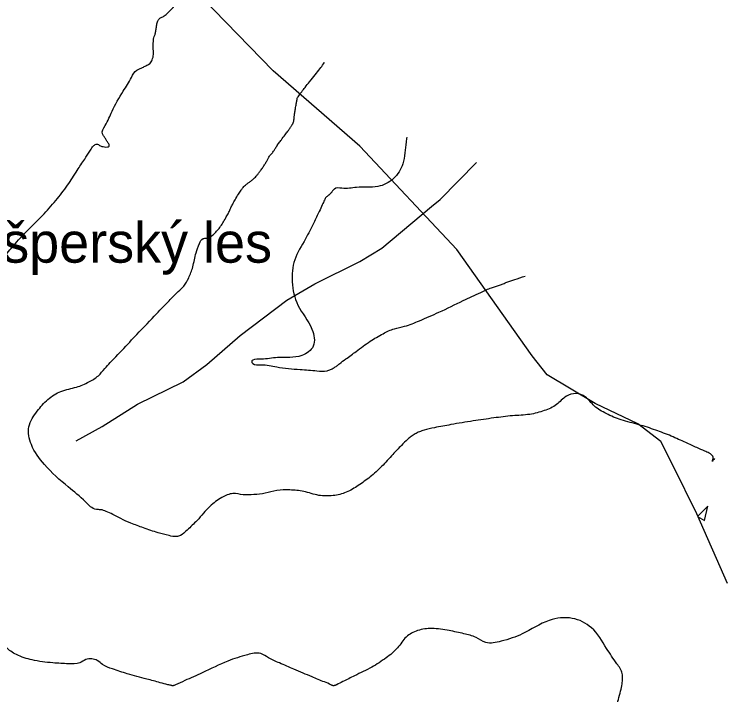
# Model space of a CAD drawing. Extents: x -478495 to -472450, y -1118050 to -1113745.
# Drawn here: x -473518.6 to -473165.3, y -1115365.2 to -1115027.8 of the extents above; entities that cross this region are included whole.
import ezdxf

# ---------------------------------------------------------------- set-up
doc = ezdxf.new("R2010")
doc.units = 0
for name, color, linetype in [('cesty', 7, 'Continuous'), ('hranice kú', 7, 'Continuous'), ('místní názvy', 7, 'Continuous'), ('ObPÚ', 7, 'Continuous'), ('vodní plochy', 7, 'Continuous'), ('Vrstevnice_vedlejsi', 7, 'Continuous')]:
    doc.layers.add(name, color=color, linetype=linetype)

msp = doc.modelspace()

# ---------------------------------------------------------------- linework, layer by layer
at = {"layer": 'cesty'}
msp.add_line((-473179.81, -1115276.83), (-473176.29, -1115278.72), dxfattribs=at)
msp.add_lwpolyline([(-473176.29, -1115278.72), (-473174.77, -1115271.65), (-473179.81, -1115276.83)], dxfattribs=at)
at = {"layer": 'hranice kú'}
for p, q in [((-473390.27, -1115055.8), (-473447.09, -1114996.95)), ((-473347.21, -1115093.26), (-473390.27, -1115055.8)), ((-473299.14, -1115144.38), (-473347.21, -1115093.26)), ((-473261.82, -1115197.18), (-473299.14, -1115144.38)), ((-473254.42, -1115206.59), (-473261.82, -1115197.18)), ((-473230.56, -1115220.72), (-473254.42, -1115206.59)), ((-473209.38, -1115230.81), (-473230.56, -1115220.72)), ((-473197.95, -1115239.55), (-473209.38, -1115230.81)), ((-473191.9, -1115251.66), (-473197.95, -1115239.55)), ((-473180.13, -1115275.53), (-473191.9, -1115251.66)), ((-473165, -1115309.94), (-473180.13, -1115275.53))]:
    msp.add_line(p, q, dxfattribs=at)
at = {"layer": 'ObPÚ'}
for p, q in [((-473390.27, -1115055.8), (-473447.09, -1114996.95)), ((-473347.21, -1115093.26), (-473390.27, -1115055.8)), ((-473299.14, -1115144.38), (-473347.21, -1115093.26)), ((-473261.82, -1115197.18), (-473299.14, -1115144.38)), ((-473254.42, -1115206.59), (-473261.82, -1115197.18)), ((-473230.56, -1115220.72), (-473254.42, -1115206.59)), ((-473209.38, -1115230.81), (-473230.56, -1115220.72)), ((-473197.95, -1115239.55), (-473209.38, -1115230.81)), ((-473191.9, -1115251.66), (-473197.95, -1115239.55)), ((-473180.13, -1115275.53), (-473191.9, -1115251.66)), ((-473165, -1115309.94), (-473180.13, -1115275.53))]:
    msp.add_line(p, q, dxfattribs=at)
at = {"layer": 'vodní plochy'}
msp.add_lwpolyline([(-473487.84, -1115239.22), (-473474.91, -1115232.13), (-473457.38, -1115221.14), (-473434.84, -1115210.01), (-473423.02, -1115201.38), (-473406.6, -1115187.05), (-473383.37, -1115169.52), (-473369.46, -1115161.45), (-473347.2, -1115150.46), (-473336.34, -1115143.79), (-473311.68, -1115123.16), (-473307.4, -1115119.58), (-473289.33, -1115101.23)], dxfattribs=at)
at = {"layer": 'Vrstevnice_vedlejsi'}
for points in [[(-473446.07, -1115029.56), (-473444.61, -1115028.92), (-473442.9, -1115027.63), (-473440.94, -1115025.69), (-473438.73, -1115023.11), (-473437.44, -1115020.95), (-473437.07, -1115019.2), (-473437.61, -1115017.87), (-473438.22, -1115015.34), (-473438.91, -1115011.62), (-473439.67, -1115006.71), (-473440.23, -1115003.19), (-473440.58, -1115001.06), (-473440.73, -1115000.32), (-473440.83, -1114999.79), (-473440.89, -1114999.47), (-473440.89, -1114999.35), (-473440.89, -1114999.26), (-473440.88, -1114999.19), (-473440.87, -1114999.14), (-473441.82, -1114996.21), (-473443.73, -1114990.4), (-473446.61, -1114981.71), (-473449.79, -1114974.48), (-473453.27, -1114968.69), (-473457.05, -1114964.34), (-473458.85, -1114958.61), (-473458.98, -1114956.64)], [(-473650.09, -1115300.41), (-473650.27, -1115300.33), (-473651.2, -1115299.89), (-473652.87, -1115299.07), (-473655.28, -1115297.89), (-473656.7, -1115296.84), (-473657.11, -1115295.91), (-473656.52, -1115295.12), (-473655.22, -1115293.42), (-473653.2, -1115290.82), (-473650.48, -1115287.31), (-473648.64, -1115284.71), (-473647.7, -1115283.01), (-473647.65, -1115282.22), (-473647.4, -1115281.54), (-473646.94, -1115280.96), (-473646.29, -1115280.49), (-473645.68, -1115279.77), (-473645.12, -1115278.79), (-473644.61, -1115277.57), (-473643.82, -1115276.53), (-473642.73, -1115275.69), (-473641.37, -1115275.03), (-473636.09, -1115270.78), (-473626.9, -1115262.92), (-473613.8, -1115251.46), (-473605.02, -1115243.63), (-473600.54, -1115239.44), (-473600.38, -1115238.88), (-473600.08, -1115237.64), (-473599.62, -1115235.74), (-473599.03, -1115233.18), (-473598.49, -1115231.28), (-473597.99, -1115230.06), (-473597.54, -1115229.51), (-473597.17, -1115229.12), (-473596.88, -1115228.88), (-473596.67, -1115228.79), (-473595.3, -1115227.08), (-473592.76, -1115223.73), (-473589.05, -1115218.76), (-473585.86, -1115213.91), (-473583.19, -1115209.19), (-473581.03, -1115204.6), (-473578.54, -1115200.48), (-473575.73, -1115196.85), (-473572.58, -1115193.71), (-473569.44, -1115191.31), (-473566.29, -1115189.66), (-473563.15, -1115188.77), (-473557.95, -1115185.07), (-473550.71, -1115178.58), (-473541.42, -1115169.29), (-473533.88, -1115161.21), (-473528.09, -1115154.34), (-473524.04, -1115148.68), (-473518.79, -1115142.34), (-473512.33, -1115135.34), (-473504.66, -1115127.67), (-473497.93, -1115120.09), (-473492.16, -1115112.61), (-473487.34, -1115105.23), (-473483.65, -1115099.59), (-473481.12, -1115095.71), (-473479.73, -1115093.58), (-473478.47, -1115092.39), (-473477.35, -1115092.14), (-473476.35, -1115092.82), (-473475.18, -1115093.3), (-473473.83, -1115093.56), (-473472.29, -1115093.61), (-473471.54, -1115093.21), (-473471.57, -1115092.35), (-473472.39, -1115091.04), (-473473.2, -1115089.74), (-473474.01, -1115088.45), (-473474.81, -1115087.18), (-473473.5, -1115083), (-473470.08, -1115075.94), (-473464.54, -1115065.97), (-473460.42, -1115059.14), (-473457.72, -1115055.46), (-473456.44, -1115054.91), (-473454.96, -1115054.2), (-473453.28, -1115053.34), (-473451.39, -1115052.32), (-473450.17, -1115050.45), (-473449.59, -1115047.74), (-473449.68, -1115044.17), (-473449.59, -1115041.4), (-473449.33, -1115039.43), (-473448.89, -1115038.24), (-473448.49, -1115036.69), (-473448.15, -1115034.77), (-473447.84, -1115032.49), (-473447.15, -1115030.75), (-473446.07, -1115029.56)], [(-473386.12, -1115090.04), (-473384.27, -1115087.59), (-473382.9, -1115085.74), (-473382.01, -1115084.5), (-473381.6, -1115083.86), (-473381.25, -1115083.31), (-473380.95, -1115082.85), (-473380.7, -1115082.48), (-473380.52, -1115082.21), (-473380.42, -1115082.04), (-473380.39, -1115081.96), (-473380.36, -1115081.9), (-473380.35, -1115081.85), (-473380.35, -1115081.81), (-473380.33, -1115081.76), (-473380.3, -1115081.69), (-473380.25, -1115081.61), (-473380.19, -1115081.48), (-473380.12, -1115081.31), (-473380.05, -1115081.1), (-473379.95, -1115080.54), (-473379.84, -1115079.64), (-473379.71, -1115078.38), (-473379.48, -1115076.73), (-473379.16, -1115074.67), (-473378.75, -1115072.21), (-473378.46, -1115070.51), (-473378.29, -1115069.57), (-473378.25, -1115069.39), (-473377.86, -1115068.77), (-473377.13, -1115067.71), (-473376.06, -1115066.21), (-473374.4, -1115064.06), (-473372.15, -1115061.26), (-473369.31, -1115057.81), (-473367.02, -1115054.86), (-473365.27, -1115052.42), (-473364.71, -1115051.53)], [(-473321.77, -1115237.12), (-473323.54, -1115238.56), (-473326.57, -1115241.52), (-473330.86, -1115246.01), (-473336.41, -1115252.02), (-473342.12, -1115257.16), (-473347.98, -1115261.42), (-473353.99, -1115264.8), (-473360.5, -1115266.43), (-473367.52, -1115266.3), (-473375.03, -1115264.42), (-473381.98, -1115263.62), (-473388.36, -1115263.89), (-473394.18, -1115265.23), (-473399.75, -1115265.93), (-473405.06, -1115265.99), (-473410.12, -1115265.41), (-473415.62, -1115267.34), (-473421.55, -1115271.78), (-473427.93, -1115278.74), (-473432.82, -1115283.55), (-473436.21, -1115286.22), (-473438.1, -1115286.75), (-473441.79, -1115286.29), (-473447.27, -1115284.85), (-473454.54, -1115282.42), (-473460.7, -1115280.09), (-473465.74, -1115277.86), (-473469.66, -1115275.72), (-473472.99, -1115274.25), (-473475.72, -1115273.45), (-473477.86, -1115273.32), (-473483.22, -1115269.54), (-473491.8, -1115262.12), (-473503.6, -1115251.06), (-473510.09, -1115241.12), (-473511.29, -1115232.31), (-473507.19, -1115224.61), (-473501.89, -1115218.77), (-473495.39, -1115214.78), (-473487.69, -1115212.64), (-473481.51, -1115210.05), (-473476.85, -1115207), (-473473.7, -1115203.5), (-473468.2, -1115197.59), (-473460.36, -1115189.28), (-473450.18, -1115178.56), (-473442.47, -1115170.55), (-473437.24, -1115165.23), (-473434.48, -1115162.62), (-473432.09, -1115158.56), (-473430.06, -1115153.07), (-473428.4, -1115146.15), (-473426.71, -1115141.47), (-473424.98, -1115139.03), (-473423.21, -1115138.85), (-473421.49, -1115138.18), (-473419.83, -1115137.03), (-473418.21, -1115135.39), (-473416.65, -1115133.47), (-473415.15, -1115131.26), (-473413.71, -1115128.76), (-473412.56, -1115126.68), (-473411.72, -1115125), (-473411.17, -1115123.73), (-473410.27, -1115121.98), (-473409.03, -1115119.76), (-473407.44, -1115117.05), (-473406.13, -1115115.01), (-473405.1, -1115113.64), (-473404.35, -1115112.93), (-473403.42, -1115112.13), (-473402.31, -1115111.25), (-473401.01, -1115110.28), (-473399.91, -1115109.38), (-473399.01, -1115108.53), (-473398.31, -1115107.74), (-473397.45, -1115106.67), (-473396.44, -1115105.32), (-473395.28, -1115103.69), (-473394.26, -1115102.13), (-473393.39, -1115100.66), (-473392.67, -1115099.25), (-473392.06, -1115098.21), (-473391.55, -1115097.53), (-473391.14, -1115097.21), (-473390.61, -1115096.59), (-473389.97, -1115095.66), (-473389.19, -1115094.44), (-473388.64, -1115093.58), (-473388.3, -1115093.09), (-473388.19, -1115092.97), (-473388.1, -1115092.84), (-473388.04, -1115092.72), (-473388.01, -1115092.6), (-473387.37, -1115091.71), (-473386.12, -1115090.04)], [(-473323.96, -1115088.79), (-473324.31, -1115091.11), (-473325.95, -1115101.92), (-473330.6, -1115109.29), (-473338.26, -1115113.21), (-473348.92, -1115113.68), (-473356.12, -1115114.09), (-473359.86, -1115114.45), (-473360.12, -1115114.75), (-473360.41, -1115115.07), (-473360.71, -1115115.42), (-473361.04, -1115115.79), (-473361.33, -1115116.12), (-473361.58, -1115116.42), (-473361.8, -1115116.68), (-473362.05, -1115116.93), (-473362.32, -1115117.18), (-473362.62, -1115117.43), (-473362.99, -1115117.74), (-473363.42, -1115118.11), (-473363.92, -1115118.56), (-473364.74, -1115119.95), (-473365.88, -1115122.27), (-473367.34, -1115125.53), (-473370.1, -1115131.18), (-473374.17, -1115139.2), (-473379.53, -1115149.6), (-473380.79, -1115160.53), (-473377.93, -1115172), (-473370.97, -1115184), (-473370.32, -1115192.34), (-473376, -1115197), (-473388, -1115198), (-473396.12, -1115198.78), (-473400.36, -1115199.34), (-473400.72, -1115199.67), (-473400.85, -1115200.04), (-473400.72, -1115200.44), (-473400.36, -1115200.89), (-473396.25, -1115201.61), (-473388.4, -1115202.62), (-473376.8, -1115203.91), (-473368.48, -1115204.55), (-473363.46, -1115204.54), (-473361.73, -1115203.9), (-473360.13, -1115203.1), (-473358.67, -1115202.17), (-473357.34, -1115201.08), (-473354.12, -1115198.68), (-473349.04, -1115194.97), (-473342.07, -1115189.93), (-473335.74, -1115186.18), (-473330.07, -1115183.69), (-473325.03, -1115182.49), (-473317.68, -1115179.76), (-473308, -1115175.52), (-473296, -1115169.76), (-473287.32, -1115165.7), (-473281.97, -1115163.36), (-473279.95, -1115162.72), (-473278, -1115162.06), (-473276.14, -1115161.39), (-473274.36, -1115160.69), (-473270.46, -1115159.33), (-473265.31, -1115157.58)], [(-473171.35, -1115248.09), (-473171.98, -1115248.94), (-473172.36, -1115249.44), (-473172.42, -1115249.51), (-473172.39, -1115249.2), (-473172.27, -1115248.5), (-473172.07, -1115247.42), (-473172.66, -1115246.37), (-473174.04, -1115245.36), (-473176.22, -1115244.39), (-473180.08, -1115242.66), (-473185.6, -1115240.18), (-473192.8, -1115236.95), (-473200.54, -1115233.99), (-473208.83, -1115231.31), (-473217.66, -1115228.9), (-473225.05, -1115225.8), (-473231, -1115221.99), (-473235.5, -1115217.49), (-473240.11, -1115215.87), (-473244.85, -1115217.14), (-473249.7, -1115221.3), (-473255.76, -1115224.3), (-473263.03, -1115226.16), (-473271.52, -1115226.87), (-473280.85, -1115227.95), (-473291.03, -1115229.41), (-473302.06, -1115231.25), (-473310.18, -1115232.77), (-473315.39, -1115233.96), (-473317.7, -1115234.82), (-473319.82, -1115235.87), (-473321.77, -1115237.12)], [(-473221.3, -1115375.36), (-473220.76, -1115373.53), (-473220.02, -1115370.91), (-473219.07, -1115367.52), (-473217.92, -1115363.34), (-473217.21, -1115359.82), (-473216.95, -1115356.94), (-473217.14, -1115354.7), (-473219.78, -1115349.79), (-473224.88, -1115342.2), (-473232.44, -1115331.92), (-473241.92, -1115327.29), (-473253.33, -1115328.31), (-473266.67, -1115334.98), (-473277.16, -1115338.62), (-473284.81, -1115339.24), (-473289.62, -1115336.83), (-473295.67, -1115334.88), (-473302.95, -1115333.36), (-473311.48, -1115332.3), (-473318.58, -1115333.36), (-473324.26, -1115336.56), (-473328.52, -1115341.89), (-473334.21, -1115346.86), (-473341.31, -1115351.48), (-473349.83, -1115355.74), (-473355.63, -1115358.64), (-473358.71, -1115360.19), (-473359.07, -1115360.39), (-473359.37, -1115360.52), (-473359.61, -1115360.61), (-473359.81, -1115360.63), (-473360.01, -1115360.65), (-473360.22, -1115360.66), (-473360.44, -1115360.66), (-473360.73, -1115360.58), (-473361.1, -1115360.44), (-473361.54, -1115360.22), (-473364.81, -1115358.83), (-473370.92, -1115356.27), (-473379.87, -1115352.54), (-473387.08, -1115349.38), (-473392.54, -1115346.78), (-473396.27, -1115344.75), (-473402.98, -1115345.31), (-473412.67, -1115348.48), (-473425.35, -1115354.24), (-473434.02, -1115358.16), (-473438.68, -1115360.25), (-473439.34, -1115360.51), (-473439.85, -1115360.66), (-473440.19, -1115360.7), (-473440.39, -1115360.64), (-473440.82, -1115360.54), (-473441.48, -1115360.39), (-473442.39, -1115360.19), (-473446.19, -1115359.19), (-473452.91, -1115357.38), (-473462.52, -1115354.76), (-473469.8, -1115352.35), (-473474.76, -1115350.17), (-473477.38, -1115348.2), (-473480.15, -1115347.4), (-473483.06, -1115347.76), (-473486.12, -1115349.29), (-473491.58, -1115349.82), (-473499.45, -1115349.35), (-473509.73, -1115347.89), (-473517.46, -1115345.25), (-473522.66, -1115341.45), (-473525.32, -1115336.49), (-473527.81, -1115332.66), (-473530.11, -1115329.97), (-473532.24, -1115328.41), (-473534.98, -1115326.6), (-473538.34, -1115324.54), (-473542.32, -1115322.22), (-473545.5, -1115320.41), (-473547.88, -1115319.11), (-473549.46, -1115318.33), (-473550.66, -1115317.71), (-473551.46, -1115317.26), (-473551.87, -1115316.98), (-473552.48, -1115316.5), (-473553.28, -1115315.81), (-473554.29, -1115314.92), (-473555.5, -1115315.16), (-473556.91, -1115316.52), (-473558.53, -1115319.01), (-473559.62, -1115321.01), (-473560.2, -1115322.54), (-473560.25, -1115323.58), (-473560.69, -1115324.71), (-473561.54, -1115325.92), (-473562.77, -1115327.21), (-473566.08, -1115329.72), (-473571.45, -1115333.46)]]:
    msp.add_spline(points, degree=3, dxfattribs=at)

# ---------------------------------------------------------------- texts
at = {"layer": 'místní názvy'}
msp.add_text('Brušperský les', height=20, rotation=360, dxfattribs=at).set_placement((-473566.15, -1115150.97))

doc.saveas('drawing.dxf')
